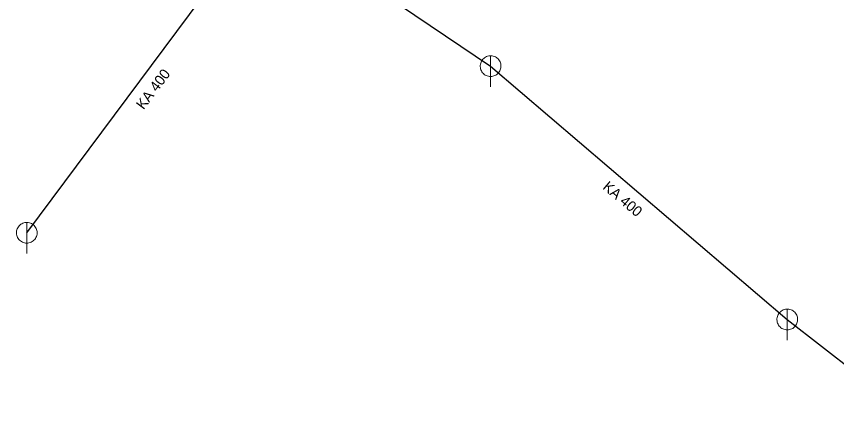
# Model space of a CAD drawing. Extents: x -790267 to -789874, y -989766 to -989454.
# Drawn here: x -790040.2 to -789961.1, y -989596.4 to -989558.8 of the extents above; entities that cross this region are included whole.
import ezdxf

# ---------------------------------------------------------------- set-up
doc = ezdxf.new("R2010")
doc.units = 0
doc.header["$LTSCALE"] = 0.4
doc.layers.add('1', color=7, linetype='Continuous')
doc.layers.add('14', color=7, linetype='Continuous', lineweight=13)
doc.layers.add('22', color=7, linetype='Continuous', lineweight=13)

msp = doc.modelspace()

# ---------------------------------------------------------------- linework, layer by layer
at = {"layer": '14', "lineweight": 25}
for p, q in [((-789994.436, -989563.595), (-789965.811, -989588.026)), ((-789965.811, -989588.026), (-789937.51, -989610.1))]:
    msp.add_line(p, q, dxfattribs=at)
msp.add_lwpolyline([(-790039.189, -989579.662), (-790016.253, -989548.866), (-789994.436, -989563.595)], dxfattribs=at)
at = {"layer": '22'}
for p, q in [((-789994.436, -989565.595), (-789994.435, -989562.595)), ((-790039.189, -989581.662), (-790039.188, -989578.662)), ((-789965.811, -989590.026), (-789965.81, -989587.026))]:
    msp.add_line(p, q, dxfattribs=at)
for points in [[(-789993.436, -989563.595), (-789993.441, -989563.486), (-789993.459, -989563.378), (-789993.489, -989563.272), (-789993.529, -989563.171), (-789993.581, -989563.074), (-789993.643, -989562.984), (-789993.715, -989562.901), (-789993.795, -989562.827), (-789993.883, -989562.761), (-789993.977, -989562.706), (-789994.077, -989562.661), (-789994.182, -989562.628), (-789994.289, -989562.606), (-789994.398, -989562.596), (-789994.508, -989562.598), (-789994.616, -989562.612), (-789994.723, -989562.637), (-789994.826, -989562.674), (-789994.924, -989562.723), (-789995.016, -989562.781), (-789995.102, -989562.85), (-789995.179, -989562.927), (-789995.248, -989563.013), (-789995.307, -989563.105), (-789995.355, -989563.203), (-789995.392, -989563.306), (-789995.418, -989563.413), (-789995.432, -989563.521), (-789995.435, -989563.631), (-789995.425, -989563.74), (-789995.404, -989563.847), (-789995.37, -989563.951), (-789995.326, -989564.051), (-789995.271, -989564.146), (-789995.205, -989564.234), (-789995.131, -989564.314), (-789995.048, -989564.386), (-789994.958, -989564.448), (-789994.862, -989564.5), (-789994.76, -989564.541), (-789994.655, -989564.571), (-789994.547, -989564.589), (-789994.437, -989564.595), (-789994.328, -989564.589), (-789994.22, -989564.571), (-789994.115, -989564.542), (-789994.013, -989564.501), (-789993.916, -989564.449), (-789993.826, -989564.387), (-789993.743, -989564.316), (-789993.668, -989564.236), (-789993.603, -989564.148), (-789993.547, -989564.054), (-789993.503, -989563.954), (-789993.469, -989563.85), (-789993.447, -989563.742), (-789993.437, -989563.633)], [(-790038.189, -989579.662), (-790038.194, -989579.553), (-790038.212, -989579.445), (-790038.242, -989579.339), (-790038.282, -989579.238), (-790038.334, -989579.141), (-790038.396, -989579.051), (-790038.468, -989578.968), (-790038.548, -989578.894), (-790038.636, -989578.828), (-790038.73, -989578.773), (-790038.83, -989578.728), (-790038.935, -989578.695), (-790039.042, -989578.673), (-790039.151, -989578.663), (-790039.261, -989578.665), (-790039.369, -989578.679), (-790039.476, -989578.704), (-790039.579, -989578.741), (-790039.677, -989578.79), (-790039.769, -989578.848), (-790039.855, -989578.917), (-790039.932, -989578.994), (-790040.001, -989579.08), (-790040.06, -989579.172), (-790040.108, -989579.27), (-790040.145, -989579.373), (-790040.171, -989579.48), (-790040.185, -989579.588), (-790040.188, -989579.698), (-790040.178, -989579.807), (-790040.157, -989579.914), (-790040.123, -989580.018), (-790040.079, -989580.118), (-790040.024, -989580.213), (-790039.958, -989580.301), (-790039.884, -989580.381), (-790039.801, -989580.453), (-790039.711, -989580.515), (-790039.615, -989580.567), (-790039.513, -989580.608), (-790039.408, -989580.638), (-790039.3, -989580.656), (-790039.19, -989580.662), (-790039.081, -989580.656), (-790038.973, -989580.638), (-790038.868, -989580.609), (-790038.766, -989580.568), (-790038.669, -989580.516), (-790038.579, -989580.454), (-790038.496, -989580.383), (-790038.421, -989580.303), (-790038.356, -989580.215), (-790038.3, -989580.121), (-790038.256, -989580.021), (-790038.222, -989579.917), (-790038.2, -989579.809), (-790038.19, -989579.7)], [(-789964.811, -989588.026), (-789964.816, -989587.917), (-789964.834, -989587.809), (-789964.864, -989587.703), (-789964.904, -989587.602), (-789964.956, -989587.505), (-789965.018, -989587.415), (-789965.09, -989587.332), (-789965.17, -989587.258), (-789965.258, -989587.192), (-789965.352, -989587.137), (-789965.452, -989587.092), (-789965.557, -989587.059), (-789965.664, -989587.037), (-789965.773, -989587.027), (-789965.883, -989587.029), (-789965.991, -989587.043), (-789966.098, -989587.068), (-789966.201, -989587.105), (-789966.299, -989587.154), (-789966.391, -989587.212), (-789966.477, -989587.281), (-789966.554, -989587.358), (-789966.623, -989587.444), (-789966.682, -989587.536), (-789966.73, -989587.634), (-789966.767, -989587.737), (-789966.793, -989587.844), (-789966.807, -989587.952), (-789966.81, -989588.062), (-789966.8, -989588.171), (-789966.779, -989588.278), (-789966.745, -989588.382), (-789966.701, -989588.482), (-789966.646, -989588.577), (-789966.58, -989588.665), (-789966.506, -989588.745), (-789966.423, -989588.817), (-789966.333, -989588.879), (-789966.237, -989588.931), (-789966.135, -989588.972), (-789966.03, -989589.002), (-789965.922, -989589.02), (-789965.812, -989589.026), (-789965.703, -989589.02), (-789965.595, -989589.002), (-789965.49, -989588.973), (-789965.388, -989588.932), (-789965.291, -989588.88), (-789965.201, -989588.818), (-789965.118, -989588.747), (-789965.043, -989588.667), (-789964.978, -989588.579), (-789964.922, -989588.485), (-789964.878, -989588.385), (-789964.844, -989588.281), (-789964.822, -989588.173), (-789964.812, -989588.064)]]:
    msp.add_lwpolyline(points, close=True, dxfattribs=at)

# ---------------------------------------------------------------- texts
at = {"layer": '1'}
for rotation, p in [(53, (-790027.919, -989567.855)), (320, (-789983.693, -989575.372))]:
    msp.add_text('KA 400', height=1, rotation=rotation, dxfattribs=at).set_placement(p)

doc.saveas('drawing.dxf')
